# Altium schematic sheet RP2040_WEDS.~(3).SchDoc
size 297 x 210 mm
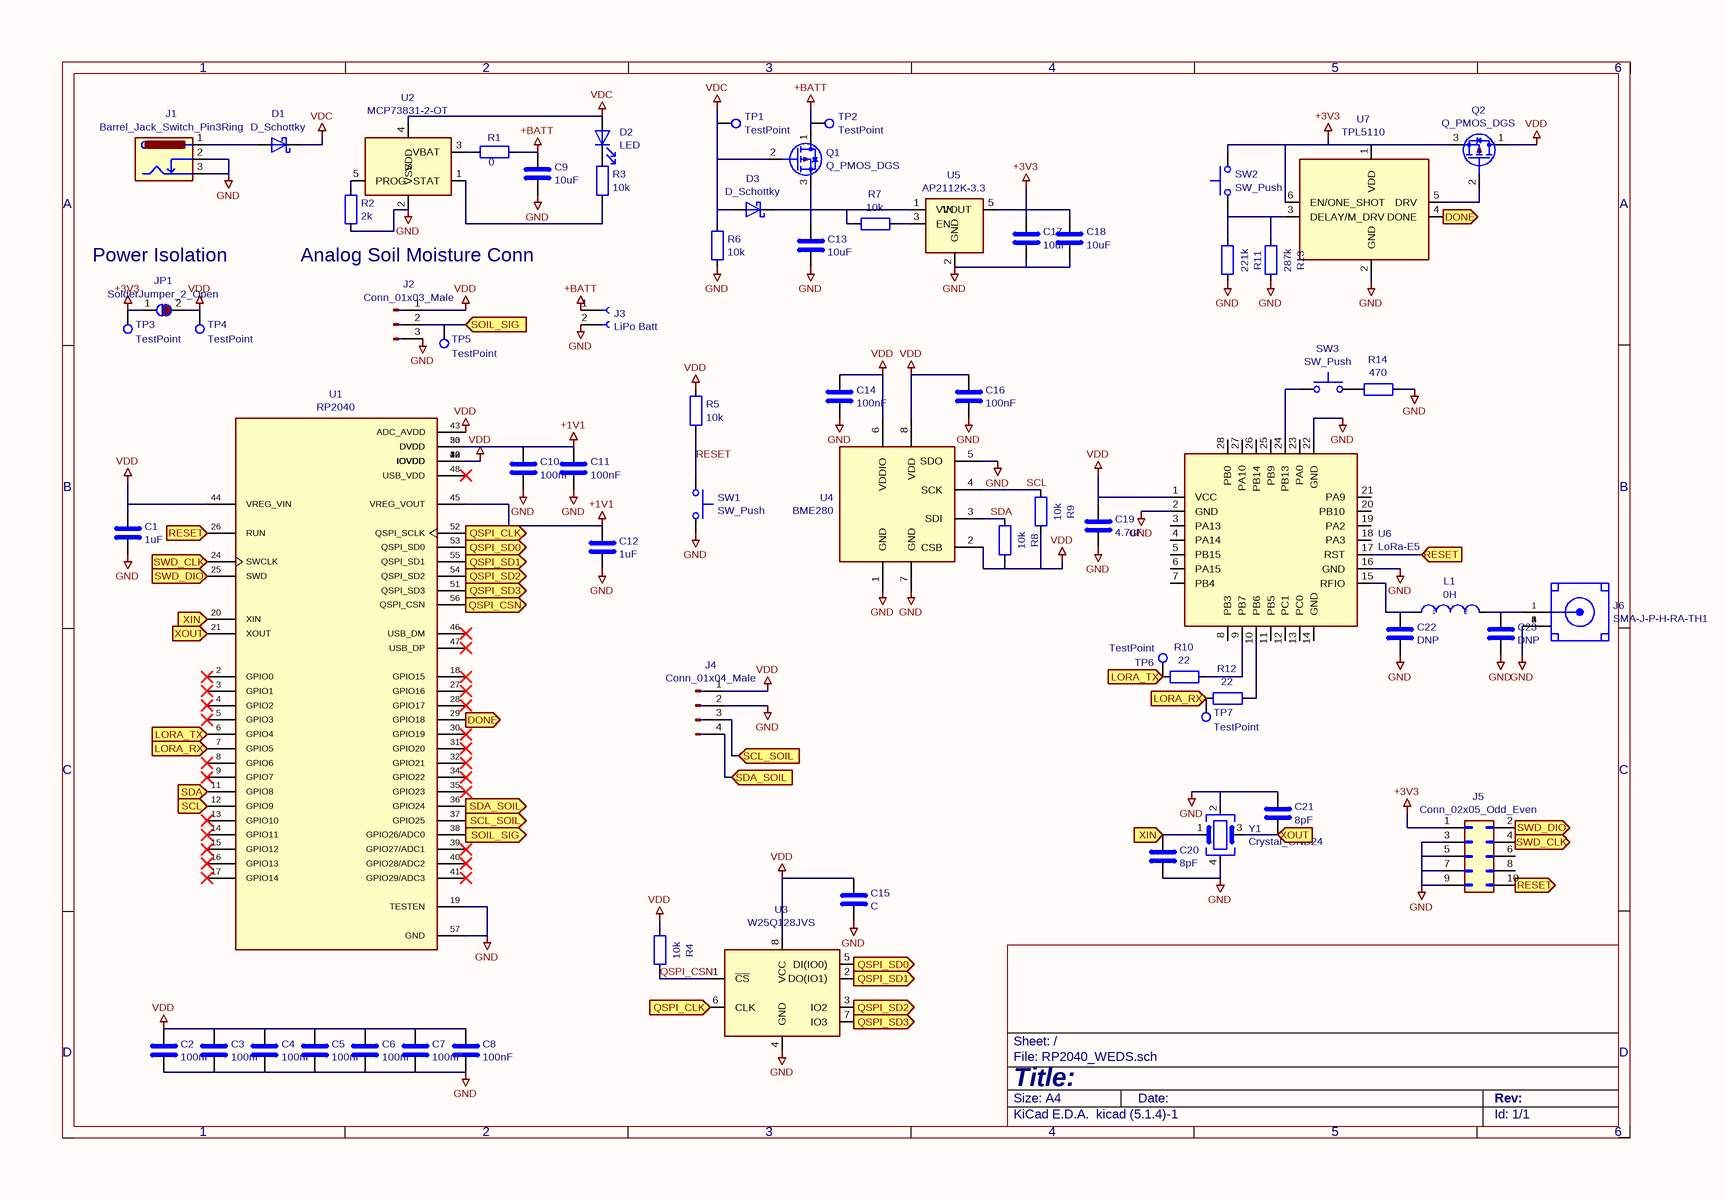
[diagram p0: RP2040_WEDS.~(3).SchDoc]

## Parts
C1  1uF  [C_0603_1608Metric]
C2  100nF  [C_0603_1608Metric]
C3  100nF  [C_0603_1608Metric]
C4  100nF  [C_0603_1608Metric]
C5  100nF  [C_0603_1608Metric]
C6  100nF  [C_0603_1608Metric]
C7  100nF  [C_0603_1608Metric]
C8  100nF  [C_0603_1608Metric]
C9  10uF  [C_0603_1608Metric]
C10  100nF  [C_0603_1608Metric]
C11  100nF  [C_0603_1608Metric]
C12  1uF  [C_0603_1608Metric]
C13  10uF  [C_0603_1608Metric]
C14  100nF  [C_0603_1608Metric]
C15  C  [C_0603_1608Metric]
C16  100nF  [C_0603_1608Metric]
C17  10uF  [C_0603_1608Metric]
C18  10uF  [C_0603_1608Metric]
C19  4.7uF  [C_0603_1608Metric]
C20  8pF  [C_0603_1608Metric]
C21  8pF  [C_0603_1608Metric]
C22  DNP  [C_0603_1608Metric]
C23  DNP  [C_0603_1608Metric]
D1  D_Schottky  [D_SOD-323]
D2  LED  [LED_0603_1608Metric]
D3  D_Schottky  [D_SOD-323]
J1  Barrel_Jack_Switch_Pin3Ring  [54-00125]
J2  Conn_01x03_Male  [PinHeader_1x03_P1.27mm_Vertical]
J3  LiPo Batt  [PinHeader_2x01_P1.27mm_Vertical]
J4  Conn_01x04_Male  [PinHeader_1x04_P1.27mm_Vertical]
J5  Conn_02x05_Odd_Even  [PinHeader_2x05_P1.27mm_Vertical_SMD]
J6  SMA-J-P-H-RA-TH1  [SMA_Amphenol_132289_EdgeMount_new]
JP1  SolderJumper_2_Open  [SolderJumper-2_P1.3mm_Open_RoundedPad1.0x1.5mm]
L1  0H  [L_0603_1608Metric]
Q1  Q_PMOS_DGS  [SOT-23]
Q2  Q_PMOS_DGS  [SOT-23]
R1  0  [R_0603_1608Metric]
R2  2k  [R_0603_1608Metric]
R3  10k  [R_0603_1608Metric]
R4  10k  [R_0603_1608Metric]
R5  10k  [R_0603_1608Metric]
R6  10k  [R_0603_1608Metric]
R7  10k  [R_0603_1608Metric]
R8  10k  [R_0603_1608Metric]
R9  10k  [R_0603_1608Metric]
R10  22  [R_0603_1608Metric]
R11  221k  [R_0603_1608Metric]
R12  22  [R_0603_1608Metric]
R13  287k  [R_0603_1608Metric]
R14  470  [R_0603_1608Metric]
SW1  SW_Push  [SW_Push_1P1T_NO_6x6mm_H9.5mm]
SW2  SW_Push  [SW_Push_1P1T_NO_6x6mm_H9.5mm]
SW3  SW_Push  [SW_Push_1P1T_NO_6x6mm_H9.5mm]
TP1  TestPoint  [TestPoint_Loop_D1.80mm_Drill1.0mm_Beaded]
TP2  TestPoint  [TestPoint_Loop_D1.80mm_Drill1.0mm_Beaded]
TP3  TestPoint  [TestPoint_Loop_D1.80mm_Drill1.0mm_Beaded]
TP4  TestPoint  [TestPoint_Loop_D1.80mm_Drill1.0mm_Beaded]
TP5  TestPoint  [TestPoint_Loop_D1.80mm_Drill1.0mm_Beaded]
TP6  TestPoint  [TestPoint_Loop_D1.80mm_Drill1.0mm_Beaded]
TP7  TestPoint  [TestPoint_Loop_D1.80mm_Drill1.0mm_Beaded]
U1  RP2040  [QFN40P700X700X90-57N]
U2  MCP73831-2-OT  [SOT-23-5]
U3  W25Q128JVS  [SOIC-8_5.23x5.23mm_P1.27mm]
U4  BME280  [Bosch_LGA-8_2.5x2.5mm_P0.65mm_ClockwisePinNumbering]
U5  AP2112K-3.3  [SOT-23-5]
U6  LoRa-E5  [LoRa-E5]
U7  TPL5110  [SOT-23-6]
Y1  Crystal_GND24  [Oscillator_SMD_Abracon_ASDMB-4Pin_2.5x2.0mm]

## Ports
DONE (in), LORA_RX (in), LORA_TX (in), QSPI_CLK (in), QSPI_CSN (in), QSPI_SD0 (in), QSPI_SD1 (in), QSPI_SD2 (in), QSPI_SD3 (in), RESET (in), SCL (in), SCL_SOIL (in), SDA (in), SDA_SOIL (in), SOIL_SIG (in), SWD_CLK (in), SWD_DIO (in), XIN (in), XOUT (in)

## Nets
+1V1: C10.1 C11.1 C12.1 U1.23(DVDD) U1.45(VREG_VOUT) U1.50(DVDD)
+3V3: C17.1 C18.1 J5.1(Pin_1) JP1.1(A) Q2.3(S) SW2.2 TP3.1 U5.5(VOUT) U7.1(VDD) U7.6(EN/ONE_SHOT)
+BATT: C9.1 J3.1(Pin_1) Q1.1(D) R1.1 TP2.1
GND: C1.2 C2.2 C3.2 C4.2 C5.2 C6.2 C7.2 C8.2 C9.2 C10.2 C11.2 C12.2 C13.2 C14.2 C15.2 C16.2 C17.2 C18.2 C19.2 C20.2 C21.1 C22.2 C23.2 J1.2 J1.3 J2.3(Pin_3) J3.2(Pin_2) J4.2(Pin_2) J5.3(Pin_3) J5.5(Pin_5) J5.7(Pin_7) J5.9(Pin_9) J6.2 J6.3 J6.4 J6.5 R2.1 R6.2 R11.1 R13.1 R14.1 SW1.2 U1.19(TESTEN) U1.57(GND) U2.2(VSS) U3.4(GND) U4.1(GND) U4.5(SDO) U4.7(GND) U5.2(GND) U6.2(GND) U6.16(GND) U6.22(GND) U7.2(GND) Y1.2 Y1.4
VDC: D1.1(K) D2.2(A) D3.2(A) Q1.2(G) R6.1 TP1.1 U2.4(VDD)
VDD: C1.1 C2.1 C3.1 C4.1 C5.1 C6.1 C7.1 C8.1 C14.1 C15.1 C16.1 C19.1 J2.1(Pin_1) J4.1(Pin_1) JP1.2(B) Q2.1(D) R4.2 R5.1 R8.1 R9.1 TP4.1 U1.1(IOVDD) U1.10(IOVDD) U1.22(IOVDD) U1.33(IOVDD) U1.42(IOVDD) U1.43(ADC_AVDD) U1.44(VREG_VIN) U1.49(IOVDD) U3.8(VCC) U4.2(CSB) U4.6(VDDIO) U4.8(VDD) U6.1(VCC)
DONE: U1.29(GPIO18) U7.4(DONE) ; port DONE
LORA_RX: R12.2 TP7.1 U1.7(GPIO5) ; port LORA_RX
LORA_TX: R10.2 TP6.1 U1.6(GPIO4) ; port LORA_TX
QSPI_CLK: U1.52(QSPI_SCLK) U3.6(CLK) ; port QSPI_CLK
QSPI_CSN: R4.1 U3.1(~{CS})
QSPI_CSN: U1.56(QSPI_CSN) ; port QSPI_CSN  [a separate net that carries the same name]
QSPI_SD0: U1.53(QSPI_SD0) U3.5(DI(IO0)) ; port QSPI_SD0
QSPI_SD1: U1.55(QSPI_SD1) U3.2(DO(IO1)) ; port QSPI_SD1
QSPI_SD2: U1.54(QSPI_SD2) U3.3(IO2) ; port QSPI_SD2
QSPI_SD3: U1.51(QSPI_SD3) U3.7(IO3) ; port QSPI_SD3
RESET: J5.10(Pin_10) U1.26(RUN) U6.17(RST) ; port RESET
RESET: R5.2 SW1.1  [a separate net that carries the same name]
SCL: R9.2 U4.4(SCK)
SCL: U1.12(GPIO9) ; port SCL  [a separate net that carries the same name]
SCL_SOIL: J4.3(Pin_3) U1.37(GPIO25) ; port SCL_SOIL
SDA: R8.2 U4.3(SDI)
SDA: U1.11(GPIO8) ; port SDA  [a separate net that carries the same name]
SDA_SOIL: J4.4(Pin_4) U1.36(GPIO24) ; port SDA_SOIL
SOIL_SIG: J2.2(Pin_2) TP5.1 U1.38(GPIO26/ADC0) ; port SOIL_SIG
SWD_CLK: J5.4(Pin_4) U1.24(SWCLK) ; port SWD_CLK
SWD_DIO: J5.2(Pin_2) U1.25(SWD) ; port SWD_DIO
XIN: C20.1 U1.20(XIN) Y1.1 ; port XIN
XOUT: C21.2 U1.21(XOUT) Y1.3 ; port XOUT
NetC13_1: C13.1 D3.1(K) Q1.3(S) R7.2 U5.1(VIN)
NetC22_1: C22.1 L1.1 U6.15(RFIO)
NetC23_1: C23.1 J6.1 L1.2
NetD1_2: D1.2(A) J1.1
NetD2_1: D2.1(K) R3.1
NetQ2_2: Q2.2(G) U7.5(DRV)
NetR1_2: R1.2 U2.3(VBAT)
NetR2_2: R2.2 U2.5(PROG)
NetR3_2: R3.2 U2.1(STAT)
NetR7_1: R7.1 U5.3(EN)
NetR10_1: R10.1 U6.9(PB7)
NetR11_2: R11.2 R13.2 SW2.1 U7.3(DELAY/M_DRV)
NetR12_1: R12.1 U6.10(PB6)
NetR14_2: R14.2 SW3.2
NetSW3_1: SW3.1 U6.24(PB13)

Not connected (* = marked no-connect by the designer): J5 6(Pin_6) 8(Pin_8); U1 2(GPIO0)* 3(GPIO1)* 4(GPIO2)* 5(GPIO3)* 8(GPIO6)* 9(GPIO7)* 13(GPIO10)* 14(GPIO11)* 15(GPIO12)* 16(GPIO13)* 17(GPIO14)* 18(GPIO15)* 27(GPIO16)* 28(GPIO17)* 30(GPIO19)* 31(GPIO20)* 32(GPIO21)* 34(GPIO22)* 35(GPIO23)* 39(GPIO27/ADC1)* 40(GPIO28/ADC2)* 41(GPIO29/ADC3)* 46(USB_DM)* 47(USB_DP)* 48(USB_VDD)*; U5 4(NC); U6 3(PA13) 4(PA14) 5(PB15) 6(PA15) 7(PB4) 8(PB3) 11(PB5) 12(PC1) 13(PC0) 14(GND) 18(PA3) 19(PA2) 20(PB10) 21(PA9) 23(PA0) 25(PB9) 26(PB14) 27(PA10) 28(PB0)

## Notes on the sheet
- Power Isolation
- (near R2) Analog Soil Moisture Conn

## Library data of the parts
C1-C14 C16-C23 = C
J3 = Conn_01x02_Female
J6 = SMA-J-P-H-RA-TH1: MANUFACTURER: Samtec
L1 = INDUCTOR
R1-R14 = R
U1 = RP2040: MANUFACTURER: Raspberry Pi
